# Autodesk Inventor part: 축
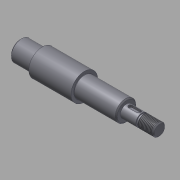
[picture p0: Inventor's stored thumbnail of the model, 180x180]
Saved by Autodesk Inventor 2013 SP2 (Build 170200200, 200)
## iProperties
Created: 2015-12
Part Number: 축
Material: 강철, 연강
Document SubType Name: Modeling
Designer: mdu
Density: 7.86 g/cm^3
CustomPartVersion: 1
Author: mdu
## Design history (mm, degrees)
sketch "스케치5"
  geometry: L1 (0, 0)-(135, 0); L2 (0, 0)-(135, 0); L3 (135, 0)-(135, 6); L4 (103, 6)-(103, 10); L5 (103, 10)-(62, 10); L6 (62, 10)-(62, 13); L7 (62, 13)-(21, 13); L8 (21, 13)-(21, 10); L9 (21, 10)-(0, 10); L10 (0, 10)-(0, 0); L11 (118, 6)-(118, 5); L12 (118, 5)-(120, 5); L13 (120, 5)-(120, 6); L14 (135, 6)-(120, 6); L15 (118, 6)-(103, 6)
  constraints: 31 end point, 12 perpendicular, 9 parallel, 1 collinear, 1 horizontal
  dimensions: "d43" = 20 diameter of L9 L1; "d44" = 26 diameter of L7 L1; "d45" = 20 diameter of L5 L2; "d47" = 41 distance of L6.end L7.end; "d48" = 32 distance between parallel lines of L3 L4; "d50" = 21 distance of L8.end L9.end; "d52" = 12 diameter of L14 L1; "d53" = 15 distance between parallel lines of L3 L13; "d54" = 2 distance of L11.end L12.end; "d55" = 1 distance between parallel lines of L14 L12; "d64" = 135 distance of L1.start L1.end
revolve "회전4" sketch "스케치5" stored, may be unused: angle "d51" = 90 deg
feature "스레드6" dims "d56" = 10, "d57" = 0
chamfer "모따기6" distance "d32" = 1; stored, may be unused: second distance "d33" = 0.4, angle "d34" = 45 deg
chamfer "모따기5" distance "d27" = 1; stored, may be unused: second distance "d28" = 0.125, angle "d29" = 45 deg
fillet "모깎기1" dims "d17" = 0.3
fillet "모깎기2" dims "d18" = 0.3
chamfer "모따기3" distance "d19" = 1; stored, may be unused: second distance "d20" = 1, angle "d21" = 45 deg
node "작업 평면1"
sketch "스케치6"
  geometry: L1 (-3.5, 2)-(4.5, 2); L2 (4.5, -2)-(-3.5, -2); L3 (-7.5, 9)-(-7.5, -9) reference; A1 r 2 centre (4.5, 0) between (4.5, -2) and (4.5, 2); A2 r 2 centre (-3.5, 0) between (-3.5, 2) and (-3.5, -2); 1 further point
  constraints: 4 end point, 4 point on circle, 4 tangent, 2 centre point, 1 horizontal, 1 horizontal alignment, 1 parallel
  dimensions: "d59" = 2 distance edge to line of A2 L3; "d60" = 12 dimension on A1 A2; "d61" = 4 distance between parallel lines of L2 L1
extrude "돌출1" cut sketch "스케치6" distance "d62" = 2.3; taper "d63" = 0 deg
node "솔리드1"
node "솔리드2"
other parameters: "d46" = 12
